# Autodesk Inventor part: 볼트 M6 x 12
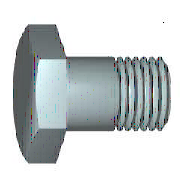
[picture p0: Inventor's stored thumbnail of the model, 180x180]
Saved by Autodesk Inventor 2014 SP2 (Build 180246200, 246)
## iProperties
IsCustomPart: 0
Created: 2012-02
Part Number: 볼트 M6 x 12
Material: 스테인리스강
Description: 6각 머리 나사. 제품 등급 C
Document SubType Name: Modeling
Standard: ISO 4018
Designer: mduedu
Standard Revision: Third edition 1999-08-15
Standards Organization: ISO
Language: ko-KR
Size Designation: M6 x 12
Categories: <MemberInstance><Categories><Category DisplayName="조임쇠" InternalName="e4da775c-781d-43d5-af7c-5136215cf5a6" Mnemonic="FSTN"><Category DisplayName="볼트" InternalN
Density: 8.08 g/cm^3
Appearance: 반광택
Author: mduedu
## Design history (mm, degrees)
node "WorkPlane1"
node "WorkPoint1"
node "MSC_A1"
node "MSC_PF1"
node "MSC_PT1"
body "Solid1"
node "스케치1"
sketch "스케치2"
  geometry: L1 (-5, 2.887)-(-5, -2.887); L2 (0, 5.773)-(-5, 2.887); L3 (5, 2.887)-(0, 5.773); L4 (5, -2.887)-(5, 2.887); L5 (0, -5.773)-(5, -2.887); L6 (-5, -2.887)-(0, -5.773); C1 r 5 at (0, 0); 1 further point
  constraints: 12 end point, 6 tangent, 2 parallel, 2 vertical, 1 centre point
  dimensions: "d1" = 10 diameter of C1 (= ParS); "d29" = 0 distance of point (0, 0) C1.centre; "d30" = 0 distance of C1.centre point (0, 0)
extrude "돌출1" new body sketch "스케치2" distance "d6" = 4 (= ParK); taper "d7" = 0 deg
revolve "회전1" stored, may be unused: angle "d14" = 360 deg
revolve "회전2" stored, may be unused: angle "d21" = 360 deg
chamfer "모따기1" distance "d22" = 0.5 (= 0.5 x PTC); stored, may be unused: second distance "d23" = 0.5 (= 0.5 x PTC), angle "d39" = 45 deg
fillet "모깎기1" dims "d24" = 0.25 (= r)
feature "스레드1" dims "d32" = 0, "b" = 10 (= NLG - 2 x PTC)
sketch "스케치3"
  geometry: L1 (5, 4)-(5.873, 4); L2 (5.873, 3.496)-(5, 4); L3 (5.873, 4)-(5.873, 3.496); L4 (0, -0.8)-(0, 4.8) reference; L5 (5.773, 0)-(5.773, 4) reference
  constraints: 6 end point, 1 horizontal, 1 vertical
  dimensions: "d25" = 0.1 distance between parallel lines of L5 L3; "d26" = 0 distance from line of L5.end L1; "d27" = 60 deg angle of L3 L2; "d28" = 5 distance from line of L4 L1.start (= 0.5 x ParS)
sketch "스케치4"
  geometry: L1 (0, -12)-(0, 0); L2 (-3, -12)-(0, -12); L3 (-3, 0)-(-3, -12); L4 (0, 0)-(-3, 0); L5 (0, -12)-(0, 0); L6 (-3.6, 0)-(0.6, 0) reference; L7 (0, -14.4)-(0, 2.4) reference
  constraints: 10 end point, 2 horizontal, 2 vertical
  dimensions: "d18" = 3 distance of L1.start L2.start (= 0.5 x NND); "d20" = 12 distance of L3.start L2.start (= NLG); "d33" = 0 distance between parallel lines of L7 L1; "d34" = 0 distance between parallel lines of L6 L4
other parameters: "NND" = 6 [user parameter; used in 2 equation terms], "NLG" = 12 [user parameter; used in 2 equation terms], "PTC" = 1 [user parameter; used in 3 equation terms], "ParK" = 4 [user parameter; used in 1 equation term], "ParS" = 10 [user parameter; used in 3 equation terms], "msp_es" = 5.77367 (= 0.577367 x ParS) [user parameter], "r" = 0.25 [user parameter; used in 1 equation term], "d2" = 15 (derived), "d4" = 17.32102 (derived), "d8" = 15 (derived), "d10" = 0 (derived), "d12" = 30 deg (derived), "d15" = 0 (derived), "d37" = 0, "d38" = 0, "d40" = 0, "d41" = 0, "d42" = 0, "THREADDIA" = 6 (= NND) [user parameter]
